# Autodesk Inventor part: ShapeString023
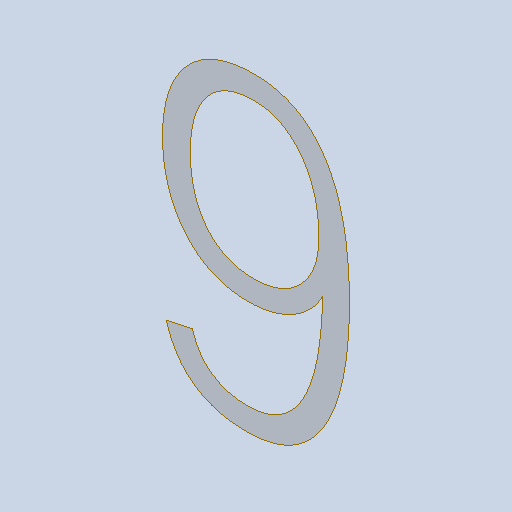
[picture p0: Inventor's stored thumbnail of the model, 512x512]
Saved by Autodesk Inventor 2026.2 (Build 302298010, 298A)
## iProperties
Created: 2026-10
Part Number: ShapeString023
Material: Générique
Document SubType Name: Modeling
Designer: mel
Density: 1 g/cm^3
Appearance: Par défaut
Author: mel
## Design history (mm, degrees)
feature "Composite1"
body "Srf1"
